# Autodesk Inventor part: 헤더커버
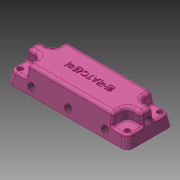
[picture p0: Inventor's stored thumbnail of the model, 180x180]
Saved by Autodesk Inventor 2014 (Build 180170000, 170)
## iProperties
Created: 2015-11
Part Number: 헤더커버
Material: 알루미늄 6061
Document SubType Name: Modeling
Designer: mduedu
Density: 2.71 g/cm^3
Mass: 159.449 g
Surface Area: 159.643 cm^2
Volume: 58.8373 cm^3
Appearance: 분홍색
Author: mduedu
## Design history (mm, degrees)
sketch "스케치1"
  geometry: L1 (52.5, 20)-(-52.5, 20); L2 (-52.5, 20)-(-52.5, -20); L3 (-52.5, -20)-(52.5, -20); L4 (52.5, -20)-(52.5, 20); L5 (52.5, 20)-(-52.5, -20); L6 (-52.5, 20)-(52.5, -20); 1 further point
  constraints: 12 end point, 2 midpoint, 2 parallel, 1 horizontal, 1 perpendicular
  dimensions: "d0" = 105 distance of L3.end L2.end; "d1" = 40 distance of L2.end L1.end
extrude "돌출1" new body sketch "스케치1" distance "d2" = 22; taper "d3" = -10 deg
sketch "스케치2"
  geometry: L1 (-48.621, -16.121)-(-48.621, 16.121) reference; L2 (-48.621, 16.121)-(48.621, 16.121) reference; L3 (48.621, 16.121)-(48.621, -16.121) reference; L4 (48.621, -16.121)-(-48.621, -16.121) reference; L5 (-37.5, 20)-(-37.5, 5); L6 (-37.5, 5)-(-52.5, 5); L7 (37.5, 20)-(37.5, 5); L8 (37.5, 5)-(52.5, 5); L9 (37.5, -20)-(37.5, -5); L10 (37.5, -5)-(52.5, -5); L11 (-37.5, -20)-(-37.5, -5); L12 (-37.5, -5)-(-52.5, -5); L13 (52.5, 20)-(-52.5, 20) reference; L14 (-52.5, -20)-(52.5, -20) reference; L15 (-52.5, 20)-(-52.5, -20) reference; L16 (52.5, -20)-(52.5, 20) reference; 5 further points
  constraints: 16 end point, 12 point on line, 7 equal length, 4 horizontal, 3 vertical
  dimensions: "d91" = 15 distance between parallel lines of L5 L15
extrude "돌출2" cut sketch "스케치2" distance "d6" = 12; taper "d7" = 0 deg
fillet "모깎기1" dims "d8" = 5
fillet "모깎기2" dims "d9" = 1
fillet "모깎기3" dims "d10" = 5
fillet "모깎기4" dims "d11" = 2
fillet "모깎기5" dims "d12" = 3
sketch "스케치3"
  geometry: L1 (-45.5, -13)-(45.5, -13); L2 (45.5, -13)-(45.5, 13); L3 (45.5, 13)-(-45.5, 13); L4 (-45.5, 13)-(-45.5, -13); L5 (-45.5, -13)-(45.5, 13); L6 (45.5, -13)-(-45.5, 13); L7 (47.576, 20)-(-47.576, 20) reference; L8 (52.5, -15.076)-(52.5, 15.076) reference; 5 further points
  constraints: 12 end point, 4 coincident, 2 midpoint, 2 parallel, 1 horizontal, 1 perpendicular
  dimensions: "d13" = 7 distance between parallel lines of L3 L7 (= d14); "d14" = 7 distance between parallel lines of L2 L8
hole "구멍1" sketch "스케치3" at (-45.5, 13), (45.5, 13), (45.5, -13), (-45.5, -13) diameter "d15" = 4.5; stored, may be unused: countersink angle "d19" = 90 deg, drill point angle "d21" = 118 deg; dims "d16" = 6, "d17" = 4, "d18" = 2, "d20" = 8
sketch "스케치4"
  geometry: L1 (47.576, -20)-(-47.576, -20) reference; L2 (52.5, 15.076)-(52.5, -15.076) reference; L3 (-47.576, 20)-(47.576, 20) reference; L4 (-52.5, -15.076)-(-52.5, 15.076) reference; L5 (-52.5, 0)-(52.5, 0); C1 r 12.25 at (0, 0); C2 r 2.25 at (45.5, 13) reference; C3 r 2.25 at (-45.5, -13) reference; C4 r 2.25 at (45.5, -13) reference; C5 r 2.25 at (-45.5, 13) reference; C6 r 12.25 at (-32, 0); C7 r 12.25 at (32, 0); 5 further points
  constraints: 3 centre point, 2 end point, 2 midpoint, 2 point on line, 1 coincident, 4 other
  dimensions: "d22" = 24.5 diameter of C1; "d23" = 24.5 diameter of C7 (= d22); "d24" = 24.5 diameter of C6 (= d22); "d25" = 32 distance of point (0, 0) C6.centre; "d26" = 32 distance of C7.centre point (0, 0) (= d25)
extrude "돌출3" cut sketch "스케치4" distance "d27" = 9; taper "d28" = 0 deg
fillet "모깎기6" dims "d29" = 5
sketch "스케치5"
  geometry: L1 (-50.031, 14)-(-43.051, 12.769); L2 (-38.312, 10.033)-(-35.04, 6.134); L3 (-49.089, 19.347)-(-50.499, 11.347) reference; L4 (-47.576, 0)-(-52.5, 0) reference; L5 (0, 0)-(0, 22); L6 (50.031, 14)-(43.051, 12.769); L7 (38.312, 10.033)-(35.04, 6.134); A1 r 8 centre (-44.44, 4.891) between (-38.312, 10.033) and (-43.051, 12.769); A2 r 8 centre (44.44, 4.891) between (43.051, 12.769) and (38.312, 10.033); 4 further points; 1 other entity
  constraints: 10 end point, 5 symmetric about line, 4 point on circle, 3 point on line, 2 centre point, 2 tangent, 1 perpendicular, 3 other
  dimensions: "d30" = 10 distance of L1.start point (-40.183, 12.264); "d32" = 140 deg angle of L2 L1; "d35" = 8 radius of A1; "d96" = 14 vertical distance of L1.start L4.end
sketch "스케치6"
  geometry: L1 (22, -2)-(22, 2) reference; L2 (11.347, -17.999)-(19.347, -16.589) reference; L3 (10.033, -5.812)-(5.684, -2.162); L4 (0, -20)-(0, -15.076) reference; L5 (12.769, -10.551)-(14, -17.531); A1 r 8 centre (4.891, -11.94) between (12.769, -10.551) and (10.033, -5.812); 2 further points
  constraints: 4 end point, 3 point on line, 2 point on circle, 2 tangent, 1 centre point, 1 perpendicular
  dimensions: "d36" = 10 distance of L5.end point (12.264, -7.683); "d40" = 8 radius of A1; "d94" = 140 deg angle of L3 L5; "d97" = 14 horizontal distance of L5.end L4.start
node "작업점1"
node "작업점2"
node "작업점3"
hole "구멍2" diameter "d43" = 5.944; stored, may be unused: countersink angle "d49" = 90 deg, drill point angle "d51" = 0 deg; dims "d41" = 10, "d42" = 10, "d44" = 6.886, "d45" = 0.62479, "d46" = 5.959, "d47" = 4, "d48" = 2, "d50" = 6.9
hole "구멍3" diameter "d54" = 5.944; stored, may be unused: countersink angle "d60" = 90 deg, drill point angle "d62" = 0 deg; dims "d55" = 6.886, "d56" = 0.62479, "d57" = 5.959, "d58" = 4, "d59" = 2, "d61" = 6.9, "d92" = 10, "d93" = 10
hole "구멍4" diameter "d65" = 5.944; stored, may be unused: countersink angle "d71" = 90 deg, drill point angle "d73" = 0 deg; dims "d63" = 10, "d64" = 10, "d66" = 6.886, "d67" = 0.62479, "d68" = 5.959, "d69" = 4, "d70" = 2, "d72" = 6.9
sketch "스케치7"
  geometry: C1 r 2.972 at (15.076, 14.216) reference; 1 further point
sketch "스케치8"
  geometry: C1 r 2.972 at (15.076, 14.216) reference; 1 further point
sketch "스케치9"
  geometry: C1 r 2.972 at (47.576, 14.216) reference; 1 further point
feature "스윕1" dims "d74" = 0
feature "스윕2" dims "d75" = 0
feature "스윕3" dims "d76" = 0
sketch "스케치10"
  geometry: L1 (15.576, 9)-(15.576, 0); L2 (47.576, 9)-(47.576, 3.473); L3 (79.576, 9)-(79.576, 0); 8 further points; 3 other entities
  constraints: 6 end point, 3 point on line, 2 horizontal alignment, 2 vertical, 2 vertical alignment, 1 parallel, 6 other
  dimensions: "d77" = 6 dimension on point (15.576, 6)
hole "구멍5" sketch "스케치10" diameter "d78" = 5.944; stored, may be unused: countersink angle "d84" = 90 deg, drill point angle "d86" = 0 deg; dims "d79" = 6.886, "d80" = 0.62479, "d81" = 5.959, "d82" = 4, "d83" = 2, "d85" = 6.9
sketch "스케치11"
  geometry: C1 r 2.972 at (0, 0) reference; C2 r 2.972 at (32, 0) reference; C3 r 2.972 at (64, 0) reference; 1 further point
extrude "돌출4" cut sketch "스케치11" distance "d87" = 8; taper "d88" = 0 deg
sketch "스케치12"
  geometry: 2 further points
  constraints: 1 coincident, 1 other
feature "엠보싱1" sketch "스케치12" dims "d0" = 105, "d1" = 40, "d9" = 1, "d89" = 0.5, "d90" = 0
node "솔리드1"
node "투영된 루프1"
node "절단 모서리 투영1"
